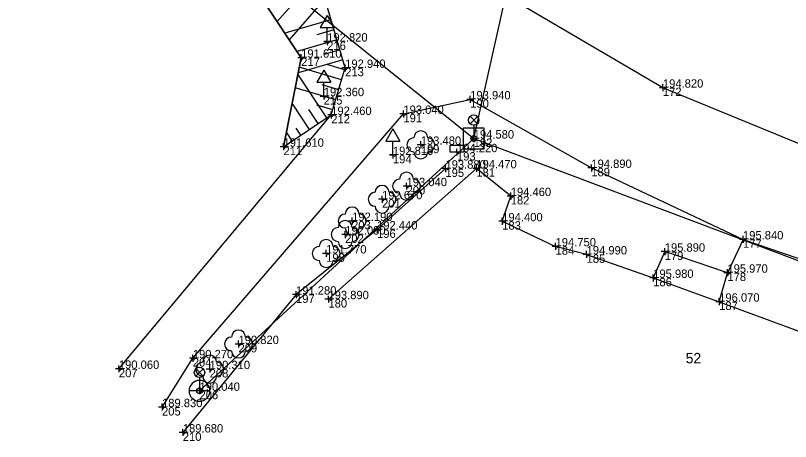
# Model space of a CAD drawing. Extents: x -744883 to -744469, y -966832 to -966374.
# Drawn here: x -744817.1 to -744761.4, y -966629.2 to -966598.7 of the extents above; entities that cross this region are included whole.
import ezdxf

# ---------------------------------------------------------------- set-up
doc = ezdxf.new("R2010")
doc.units = 0
for name, color, linetype in [('Body - výška', 7, 'Continuous'), ('Body - značka', 7, 'Continuous'), ('Body - číslo', 7, 'Continuous'), ('Body polohopisu', 7, 'Continuous'), ('Budovy', 7, 'Continuous'), ('Doplňkové značky', 7, 'Continuous'), ('Ploty_opěrné zdi', 7, 'Continuous'), ('Rozhraní ploch', 7, 'Continuous'), ('Stromy_porost', 7, 'Continuous'), ('Vrstva 132', 7, 'Continuous'), ('Vstup na pozemek', 7, 'Continuous'), ('Výškopis', 7, 'Continuous'), ('Výšky bodů', 7, 'Continuous'), ('Značky IS', 7, 'Continuous'), ('Čísla bodů', 7, 'Continuous'), ('Čísla popisná_parcelní', 7, 'Continuous')]:
    doc.layers.add(name, color=color, linetype=linetype)

msp = doc.modelspace()

# ---------------------------------------------------------------- linework, layer by layer
at = {"layer": 'Body - značka'}
for q in [(-744785.62, -966608.46), (-744785.37, -966608.21), (-744785.12, -966608.46), (-744785.37, -966608.71)]:
    msp.add_line((-744785.37, -966608.46), q, dxfattribs=at)
at = {"layer": 'Body polohopisu'}
for p, q in [((-744794.69, -966600.52), (-744794.69, -966600.27)), ((-744794.69, -966600.52), (-744794.94, -966600.52)), ((-744794.69, -966600.52), (-744794.44, -966600.52)), ((-744794.69, -966600.52), (-744794.69, -966600.77)), ((-744796.56, -966601.68), (-744796.81, -966601.68)), ((-744796.56, -966601.68), (-744796.56, -966601.43)), ((-744796.56, -966601.68), (-744796.31, -966601.68)), ((-744796.56, -966601.68), (-744796.56, -966601.93)), ((-744793.4, -966602.41), (-744793.65, -966602.41)), ((-744793.4, -966602.41), (-744793.4, -966602.16)), ((-744793.4, -966602.41), (-744793.15, -966602.41)), ((-744793.4, -966602.41), (-744793.4, -966602.66)), ((-744770.58, -966603.83), (-744770.58, -966603.58)), ((-744770.58, -966603.83), (-744770.83, -966603.83)), ((-744770.58, -966603.83), (-744770.33, -966603.83)), ((-744770.58, -966603.83), (-744770.58, -966604.08)), ((-744794.94, -966604.44), (-744795.19, -966604.44)), ((-744794.94, -966604.44), (-744794.94, -966604.19)), ((-744794.94, -966604.44), (-744794.69, -966604.44)), ((-744794.94, -966604.44), (-744794.94, -966604.69)), ((-744784.42, -966604.67), (-744784.67, -966604.67)), ((-744784.42, -966604.67), (-744784.42, -966604.42)), ((-744784.42, -966604.67), (-744784.17, -966604.67)), ((-744784.42, -966604.67), (-744784.42, -966604.92)), ((-744794.4, -966605.79), (-744794.65, -966605.79)), ((-744794.4, -966605.79), (-744794.4, -966605.54)), ((-744794.4, -966605.79), (-744794.15, -966605.79)), ((-744794.4, -966605.79), (-744794.4, -966606.04)), ((-744789.22, -966605.71), (-744789.47, -966605.71)), ((-744789.22, -966605.71), (-744789.22, -966605.46)), ((-744789.22, -966605.71), (-744788.97, -966605.71)), ((-744789.22, -966605.71), (-744789.22, -966605.96)), ((-744784.17, -966607.48), (-744784.42, -966607.48)), ((-744784.17, -966607.48), (-744784.17, -966607.23)), ((-744784.17, -966607.48), (-744783.92, -966607.48)), ((-744784.17, -966607.48), (-744784.17, -966607.73)), ((-744797.83, -966608.07), (-744797.83, -966607.82)), ((-744787.97, -966607.93), (-744788.22, -966607.93)), ((-744787.97, -966607.93), (-744787.97, -966607.68)), ((-744787.97, -966607.93), (-744787.72, -966607.93)), ((-744787.97, -966607.93), (-744787.97, -966608.18)), ((-744797.83, -966608.07), (-744798.08, -966608.07)), ((-744797.83, -966608.07), (-744797.58, -966608.07)), ((-744797.83, -966608.07), (-744797.83, -966608.32)), ((-744789.97, -966608.66), (-744789.97, -966608.41)), ((-744789.97, -966608.66), (-744790.22, -966608.66)), ((-744789.97, -966608.66), (-744789.72, -966608.66)), ((-744789.97, -966608.66), (-744789.97, -966608.91)), ((-744786.2, -966609.64), (-744786.45, -966609.64)), ((-744786.2, -966609.64), (-744786.2, -966609.39)), ((-744786.2, -966609.64), (-744785.95, -966609.64)), ((-744786.2, -966609.64), (-744786.2, -966609.89)), ((-744783.98, -966609.62), (-744784.23, -966609.62)), ((-744783.98, -966609.62), (-744783.98, -966609.37)), ((-744783.98, -966609.62), (-744783.73, -966609.62)), ((-744783.98, -966609.62), (-744783.98, -966609.87)), ((-744775.72, -966609.59), (-744775.97, -966609.59)), ((-744775.72, -966609.59), (-744775.72, -966609.34)), ((-744775.72, -966609.59), (-744775.47, -966609.59)), ((-744775.72, -966609.59), (-744775.72, -966609.84)), ((-744788.99, -966610.9), (-744788.99, -966610.65)), ((-744788.99, -966610.9), (-744789.24, -966610.9)), ((-744788.99, -966610.9), (-744788.74, -966610.9)), ((-744788.99, -966610.9), (-744788.99, -966611.15)), ((-744781.51, -966611.61), (-744781.51, -966611.36)), ((-744790.75, -966611.84), (-744791, -966611.84)), ((-744790.75, -966611.84), (-744790.75, -966611.59)), ((-744790.75, -966611.84), (-744790.5, -966611.84)), ((-744790.75, -966611.84), (-744790.75, -966612.09)), ((-744781.51, -966611.61), (-744781.76, -966611.61)), ((-744781.51, -966611.61), (-744781.26, -966611.61)), ((-744781.51, -966611.61), (-744781.51, -966611.86)), ((-744792.9, -966613.4), (-744793.15, -966613.4)), ((-744792.9, -966613.4), (-744792.9, -966613.15)), ((-744792.9, -966613.4), (-744792.65, -966613.4)), ((-744792.9, -966613.4), (-744792.9, -966613.65)), ((-744782.12, -966613.42), (-744782.37, -966613.42)), ((-744782.12, -966613.42), (-744782.12, -966613.17)), ((-744782.12, -966613.42), (-744781.87, -966613.42)), ((-744782.12, -966613.42), (-744782.12, -966613.67)), ((-744793.4, -966614.37), (-744793.4, -966614.12)), ((-744791.11, -966614.01), (-744791.36, -966614.01)), ((-744791.11, -966614.01), (-744791.11, -966613.76)), ((-744791.11, -966614.01), (-744790.86, -966614.01)), ((-744791.11, -966614.01), (-744791.11, -966614.26)), ((-744793.4, -966614.37), (-744793.65, -966614.37)), ((-744793.4, -966614.37), (-744793.15, -966614.37)), ((-744793.4, -966614.37), (-744793.4, -966614.62)), ((-744764.83, -966614.72), (-744765.08, -966614.72)), ((-744764.83, -966614.72), (-744764.83, -966614.47)), ((-744764.83, -966614.72), (-744764.58, -966614.72)), ((-744764.83, -966614.72), (-744764.83, -966614.97)), ((-744778.29, -966615.22), (-744778.54, -966615.22)), ((-744778.29, -966615.22), (-744778.29, -966614.97)), ((-744778.29, -966615.22), (-744778.04, -966615.22)), ((-744778.29, -966615.22), (-744778.29, -966615.47)), ((-744794.77, -966615.73), (-744795.02, -966615.73)), ((-744794.77, -966615.73), (-744794.77, -966615.48)), ((-744794.77, -966615.73), (-744794.52, -966615.73)), ((-744794.77, -966615.73), (-744794.77, -966615.98)), ((-744776.06, -966615.8), (-744776.31, -966615.8)), ((-744776.06, -966615.8), (-744776.06, -966615.55)), ((-744776.06, -966615.8), (-744775.81, -966615.8)), ((-744776.06, -966615.8), (-744776.06, -966616.05)), ((-744770.45, -966615.6), (-744770.7, -966615.6)), ((-744770.45, -966615.6), (-744770.45, -966615.35)), ((-744770.45, -966615.6), (-744770.2, -966615.6)), ((-744770.45, -966615.6), (-744770.45, -966615.85)), ((-744765.95, -966617.11), (-744765.95, -966616.86)), ((-744771.28, -966617.48), (-744771.53, -966617.48)), ((-744771.28, -966617.48), (-744771.28, -966617.23)), ((-744771.28, -966617.48), (-744771.03, -966617.48)), ((-744771.28, -966617.48), (-744771.28, -966617.73)), ((-744765.95, -966617.11), (-744766.2, -966617.11)), ((-744765.95, -966617.11), (-744765.7, -966617.11)), ((-744765.95, -966617.11), (-744765.95, -966617.36)), ((-744796.93, -966618.68), (-744796.93, -966618.43)), ((-744796.93, -966618.68), (-744797.18, -966618.68)), ((-744796.93, -966618.68), (-744796.68, -966618.68)), ((-744796.93, -966618.68), (-744796.93, -966618.93)), ((-744794.6, -966619.01), (-744794.85, -966619.01)), ((-744794.6, -966619.01), (-744794.6, -966618.76)), ((-744794.6, -966619.01), (-744794.35, -966619.01)), ((-744794.6, -966619.01), (-744794.6, -966619.26)), ((-744766.54, -966619.19), (-744766.79, -966619.19)), ((-744766.54, -966619.19), (-744766.54, -966618.94)), ((-744766.54, -966619.19), (-744766.29, -966619.19)), ((-744766.54, -966619.19), (-744766.54, -966619.44)), ((-744801.06, -966622.23), (-744801.06, -966621.98)), ((-744801.06, -966622.23), (-744801.31, -966622.23)), ((-744801.06, -966622.23), (-744800.81, -966622.23)), ((-744801.06, -966622.23), (-744801.06, -966622.48)), ((-744804.34, -966623.25), (-744804.34, -966623)), ((-744804.34, -966623.25), (-744804.59, -966623.25)), ((-744804.34, -966623.25), (-744804.09, -966623.25)), ((-744804.34, -966623.25), (-744804.34, -966623.5)), ((-744809.65, -966624.01), (-744809.9, -966624.01)), ((-744809.65, -966624.01), (-744809.65, -966623.76)), ((-744809.65, -966624.01), (-744809.4, -966624.01)), ((-744809.65, -966624.01), (-744809.65, -966624.26)), ((-744803.13, -966624.03), (-744803.38, -966624.03)), ((-744803.13, -966624.03), (-744803.13, -966623.78)), ((-744803.13, -966624.03), (-744802.88, -966624.03)), ((-744803.13, -966624.03), (-744803.13, -966624.28)), ((-744803.86, -966625.59), (-744804.11, -966625.59)), ((-744803.86, -966625.59), (-744803.86, -966625.34)), ((-744803.86, -966625.59), (-744803.61, -966625.59)), ((-744803.86, -966625.59), (-744803.86, -966625.84)), ((-744806.55, -966626.76), (-744806.8, -966626.76)), ((-744806.55, -966626.76), (-744806.55, -966626.51)), ((-744806.55, -966626.76), (-744806.3, -966626.76)), ((-744806.55, -966626.76), (-744806.55, -966627.01)), ((-744805.06, -966628.58), (-744805.31, -966628.58)), ((-744805.06, -966628.58), (-744805.06, -966628.33)), ((-744805.06, -966628.58), (-744804.81, -966628.58)), ((-744805.06, -966628.58), (-744805.06, -966628.83))]:
    msp.add_line(p, q, dxfattribs=at)
at = {"layer": 'Budovy'}
msp.add_lwpolyline([(-744776.06, -966615.8), (-744771.28, -966617.48), (-744766.54, -966619.19), (-744754.45, -966623.65)], dxfattribs=at)
at = {"layer": 'Doplňkové značky'}
for p, q in [((-744794.69, -966598.654), (-744795.19, -966599.52)), ((-744794.69, -966598.654), (-744794.19, -966599.52)), ((-744795.19, -966599.52), (-744794.19, -966599.52)), ((-744794.69, -966600.52), (-744794.69, -966599.52)), ((-744794.94, -966600.52), (-744794.44, -966600.52)), ((-744794.94, -966602.574), (-744795.44, -966603.44)), ((-744794.94, -966602.574), (-744794.44, -966603.44)), ((-744795.44, -966603.44), (-744794.44, -966603.44)), ((-744794.94, -966604.44), (-744794.94, -966603.44)), ((-744795.19, -966604.44), (-744794.69, -966604.44)), ((-744784.434, -966606.418), (-744783.906, -966605.89)), ((-744783.898, -966606.415), (-744784.426, -966605.886)), ((-744789.97, -966606.794), (-744790.47, -966607.66)), ((-744789.97, -966606.794), (-744789.47, -966607.66)), ((-744784.17, -966606.53), (-744784.17, -966607.28)), ((-744790.47, -966607.66), (-744789.47, -966607.66)), ((-744789.97, -966608.66), (-744789.97, -966607.66)), ((-744790.22, -966608.66), (-744789.72, -966608.66)), ((-744804.124, -966624.528), (-744803.596, -966624)), ((-744803.588, -966624.525), (-744804.116, -966623.996)), ((-744803.86, -966624.64), (-744803.86, -966625.39))]:
    msp.add_line(p, q, dxfattribs=at)
for centre, radius in [((-744784.17, -966606.155), 0.375), ((-744784.17, -966607.48), 0.2), ((-744803.86, -966624.265), 0.375), ((-744803.86, -966625.59), 0.2)]:
    msp.add_circle(centre, radius, dxfattribs=at)
at = {"layer": 'Ploty_opěrné zdi'}
for points in [[(-744797.83, -966608.07), (-744796.56, -966601.68), (-744799.21, -966597.69), (-744825.83, -966574.07), (-744838.86, -966562.47)], [(-744786.2, -966609.64), (-744791.11, -966614.01), (-744796.93, -966618.68)], [(-744782.12, -966613.42), (-744781.51, -966611.61), (-744783.98, -966609.62), (-744794.6, -966619.01)], [(-744776.06, -966615.8), (-744778.29, -966615.22)], [(-744796.93, -966618.68), (-744805.06, -966628.58)]]:
    msp.add_lwpolyline(points, dxfattribs=at)
at = {"layer": 'Rozhraní ploch'}
for points in [[(-744809.65, -966624.01), (-744794.4, -966605.79), (-744793.4, -966602.41), (-744794.75, -966597.84), (-744825.34, -966571.24), (-744838.68, -966559.82), (-744847.92, -966551.74), (-744849.33, -966553.16)], [(-744656.07, -966650.16), (-744662.8, -966644.01), (-744672.73, -966638.23), (-744685.11, -966632.67), (-744699.67, -966627.63), (-744718.38, -966621.41), (-744745.96, -966612.84), (-744758.4, -966608.84), (-744770.58, -966603.83), (-744782.97, -966596.56), (-744784.85, -966594.86)], [(-744806.55, -966626.76), (-744804.34, -966623.25), (-744789.22, -966605.71), (-744784.42, -966604.67), (-744775.72, -966609.59), (-744764.83, -966614.72), (-744765.95, -966617.11)], [(-744764.83, -966614.72), (-744753.19, -966618.69)], [(-744766.54, -966619.19), (-744765.95, -966617.11), (-744770.45, -966615.6), (-744771.28, -966617.48), (-744766.54, -966619.19)]]:
    msp.add_lwpolyline(points, dxfattribs=at)
at = {"layer": 'Stromy_porost'}
for centre in [(-744787.97, -966607.93), (-744788.99, -966610.9), (-744790.75, -966611.84), (-744792.9, -966613.4), (-744793.4, -966614.37), (-744794.77, -966615.73), (-744801.06, -966622.23), (-744803.13, -966624.03)]:
    msp.add_circle(centre, 0.0005, dxfattribs=at)
for centre, start, end in [((-744787.97, -966607.43), 0, 180), ((-744788.47, -966607.93), 90, 270), ((-744787.47, -966607.93), 270, 90), ((-744787.97, -966608.43), 180, 360), ((-744788.99, -966610.4), 0, 180), ((-744790.75, -966611.34), 0, 180), ((-744789.49, -966610.9), 90, 270), ((-744788.49, -966610.9), 270, 90), ((-744791.25, -966611.84), 90, 270), ((-744790.25, -966611.84), 270, 90), ((-744788.99, -966611.4), 180, 360), ((-744792.9, -966612.9), 0, 180), ((-744790.75, -966612.34), 180, 360), ((-744793.4, -966613.4), 90, 270), ((-744792.4, -966613.4), 270, 90), ((-744793.4, -966613.87), 0, 180), ((-744793.9, -966614.37), 90, 270), ((-744792.9, -966613.9), 180, 360), ((-744792.9, -966614.37), 270, 90), ((-744794.77, -966615.23), 0, 180), ((-744795.27, -966615.73), 90, 270), ((-744794.27, -966615.73), 270, 90), ((-744793.4, -966614.87), 180, 360), ((-744794.77, -966616.23), 180, 360), ((-744801.06, -966621.73), 0, 180), ((-744801.56, -966622.23), 90, 270), ((-744800.56, -966622.23), 270, 90), ((-744803.13, -966623.53), 0, 180), ((-744801.06, -966622.73), 180, 360), ((-744803.63, -966624.03), 90, 270), ((-744802.63, -966624.03), 270, 90), ((-744803.13, -966624.53), 180, 360)]:
    msp.add_arc(centre, 0.5, start, end, dxfattribs=at)
at = {"layer": 'Vrstva 132'}
for points in [[(-744784.17, -966607.48), (-744776.1, -966571.48), (-744766.46, -966535.83), (-744760.61, -966514.26), (-744741.19, -966482.43), (-744714.51, -966441.91), (-744696.14, -966413.51)], [(-744877.13, -966529.66), (-744852.31, -966550.13), (-744834.41, -966566.54), (-744810.37, -966586.41), (-744784.17, -966607.48)], [(-744803.86, -966625.59), (-744784.17, -966607.48)], [(-744784.17, -966607.48), (-744744.28, -966622.47), (-744705.89, -966635.13)]]:
    msp.add_lwpolyline(points, dxfattribs=at)
at = {"layer": 'Vstup na pozemek'}
msp.add_lwpolyline([(-744782.12, -966613.42), (-744778.29, -966615.22)], dxfattribs=at)
at = {"layer": 'Výškopis'}
for points in [[(-744797.83, -966608.07), (-744794.4, -966605.79), (-744793.4, -966602.41), (-744794.75, -966597.84), (-744825.34, -966571.24), (-744838.68, -966559.82), (-744847.92, -966551.74)], [(-744848.47, -966552.52), (-744840.41, -966559.08), (-744838.86, -966562.47), (-744825.83, -966574.07), (-744799.21, -966597.69), (-744796.56, -966601.68), (-744797.83, -966608.07)], [(-744796.139, -966596.632), (-744798.279, -966599.092)], [(-744795.008, -966597.616), (-744797.418, -966600.388)], [(-744794.422, -966598.951), (-744797.724, -966599.927)], [(-744794.209, -966599.671), (-744795.442, -966600.035)], [(-744793.997, -966600.39), (-744796.856, -966601.234)], [(-744793.784, -966601.109), (-744794.916, -966601.443)], [(-744793.572, -966601.828), (-744796.778, -966602.775)], [(-744793.653, -966603.267), (-744796.696, -966602.366)], [(-744793.441, -966602.548), (-744794.707, -966602.173)], [(-744794.707, -966605.994), (-744796.794, -966602.855)], [(-744794.079, -966604.705), (-744796.99, -966603.844)], [(-744793.866, -966603.986), (-744795.057, -966603.634)], [(-744795.956, -966606.824), (-744797.208, -966604.941)], [(-744794.292, -966605.424), (-744795.43, -966605.088)], [(-744795.332, -966606.409), (-744795.999, -966605.405)], [(-744796.581, -966607.24), (-744796.915, -966606.737)], [(-744797.205, -966607.655), (-744797.623, -966607.027)], [(-744797.83, -966608.07), (-744797.83, -966608.07)]]:
    msp.add_lwpolyline(points, dxfattribs=at)
at = {"layer": 'Značky IS'}
msp.add_line((-744803.113, -966625.59), (-744804.608, -966625.59), dxfattribs=at)
for points in [[(-744784.92, -966608.23), (-744783.42, -966608.23), (-744783.42, -966606.73), (-744784.92, -966606.73)], [(-744785.87, -966608.46), (-744785.87, -966607.96), (-744784.87, -966607.96), (-744784.87, -966608.46)]]:
    msp.add_lwpolyline(points, close=True, dxfattribs=at)
for start, end in [(0, 180), (180, 0)]:
    msp.add_arc((-744803.86, -966625.59), 0.747, start, end, dxfattribs=at)

# ---------------------------------------------------------------- texts
at = {"layer": 'Body - výška'}
msp.add_text('194.220', height=0.6, dxfattribs=at).set_placement((-744785.37, -966608.46))
at = {"layer": 'Body - číslo'}
msp.add_text('193', height=0.6, dxfattribs=at).set_placement((-744785.37, -966609.06))
at = {"layer": 'Výšky bodů'}
for s, p in [('192.820', (-744794.69, -966600.52)), ('191.610', (-744796.56, -966601.68)), ('192.940', (-744793.4, -966602.41)), ('194.820', (-744770.58, -966603.83)), ('192.360', (-744794.94, -966604.44)), ('193.940', (-744784.42, -966604.67)), ('192.460', (-744794.4, -966605.79)), ('193.040', (-744789.22, -966605.71)), ('194.580', (-744784.17, -966607.48)), ('191.610', (-744797.83, -966608.07)), ('193.480', (-744787.97, -966607.93)), ('192.810', (-744789.97, -966608.66)), ('193.880', (-744786.2, -966609.64)), ('194.470', (-744783.98, -966609.62)), ('194.890', (-744775.72, -966609.59)), ('193.040', (-744788.99, -966610.9)), ('192.670', (-744790.75, -966611.84)), ('194.460', (-744781.51, -966611.61)), ('192.190', (-744792.9, -966613.4)), ('194.400', (-744782.12, -966613.42)), ('192.440', (-744791.11, -966614.01)), ('192.080', (-744793.4, -966614.37)), ('195.840', (-744764.83, -966614.72)), ('194.750', (-744778.29, -966615.22)), ('191.770', (-744794.77, -966615.73)), ('194.990', (-744776.06, -966615.8)), ('195.890', (-744770.45, -966615.6)), ('195.980', (-744771.28, -966617.48)), ('195.970', (-744765.95, -966617.11)), ('191.280', (-744796.93, -966618.68)), ('193.890', (-744794.6, -966619.01)), ('196.070', (-744766.54, -966619.19)), ('190.820', (-744801.06, -966622.23)), ('190.270', (-744804.34, -966623.25)), ('190.060', (-744809.65, -966624.01)), ('190.310', (-744803.13, -966624.03)), ('190.040', (-744803.86, -966625.59)), ('189.830', (-744806.55, -966626.76)), ('189.680', (-744805.06, -966628.58))]:
    msp.add_text(s, height=0.6, dxfattribs=at).set_placement(p)
at = {"layer": 'Čísla bodů'}
for s, p in [('216', (-744794.69, -966601.12)), ('217', (-744796.56, -966602.28)), ('213', (-744793.4, -966603.01)), ('172', (-744770.58, -966604.43)), ('215', (-744794.94, -966605.04)), ('190', (-744784.42, -966605.27)), ('212', (-744794.4, -966606.39)), ('191', (-744789.22, -966606.31)), ('192', (-744784.17, -966608.08)), ('211', (-744797.83, -966608.67)), ('199', (-744787.97, -966608.53)), ('194', (-744789.97, -966609.26)), ('195', (-744786.2, -966610.24)), ('181', (-744783.98, -966610.22)), ('189', (-744775.72, -966610.19)), ('200', (-744788.99, -966611.5)), ('201', (-744790.75, -966612.44)), ('182', (-744781.51, -966612.21)), ('203', (-744792.9, -966614)), ('183', (-744782.12, -966614.02)), ('196', (-744791.11, -966614.61)), ('202', (-744793.4, -966614.97)), ('177', (-744764.83, -966615.32)), ('184', (-744778.29, -966615.82)), ('198', (-744794.77, -966616.33)), ('185', (-744776.06, -966616.4)), ('179', (-744770.45, -966616.2)), ('186', (-744771.28, -966618.08)), ('178', (-744765.95, -966617.71)), ('197', (-744796.93, -966619.28)), ('180', (-744794.6, -966619.61)), ('187', (-744766.54, -966619.79)), ('209', (-744801.06, -966622.83)), ('204', (-744804.34, -966623.85)), ('207', (-744809.65, -966624.61)), ('208', (-744803.13, -966624.63)), ('206', (-744803.86, -966626.19)), ('205', (-744806.55, -966627.36)), ('210', (-744805.06, -966629.18))]:
    msp.add_text(s, height=0.6, dxfattribs=at).set_placement(p)
at = {"layer": 'Čísla popisná_parcelní'}
msp.add_text('52', height=0.75, dxfattribs=at).set_placement((-744768.946, -966623.617))

doc.saveas('drawing.dxf')
